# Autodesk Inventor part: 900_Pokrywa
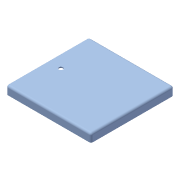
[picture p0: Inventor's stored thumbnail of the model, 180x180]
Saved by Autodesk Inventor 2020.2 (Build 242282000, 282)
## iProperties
Created: 2006-01
Part Number: 900_Pokrywa
Document SubType Name: Modeling
Designer: F.Stasiak
Density: 1 g/cm^3
Material: Ogólny
Appearance: Niebieski pastelowy
Manager: www.cadconsulting.pl
Company: Fabian Stasiak CAD Consulting
Author: F.Stasiak
Subject: Zbiór ćwiczeń. Autodesk Inventor 2020. Kurs podstawowy
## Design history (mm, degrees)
sketch "Szkic1"
  geometry: L1 (205, 200)-(-205, 200); L2 (-205, 200)-(-205, -200); L3 (-205, -200)-(205, -200); L4 (205, -200)-(205, 200); L5 (205, 0)-(-205, 0); 2 further points
  constraints: 10 end point, 3 midpoint, 2 parallel, 1 coincident, 1 horizontal, 1 perpendicular
  dimensions: "d0" = 410 distance of L2.end L3.end; "d1" = 400 distance of L1.end L2.end
extrude "Wyciągnięcie proste1" new body sketch "Szkic1" distance "d2" = 40; taper "d3" = 0 deg
fillet "Zaokrąglenie1" dims "d4" = 10
feature "Skorupa1" dims "d5" = 5
sketch "Szkic2"
  geometry: C1 r 10 at (-140, 0); 1 further point
  constraints: 1 centre point
  dimensions: "d6" = 20 diameter of C1; "d7" = 140 distance of point (0, 0) C1.centre; "d8" = 0 vertical distance of point (0, 0) C1.centre
extrude "Wyciągnięcie proste2" cut sketch "Szkic2" extent not by distance; stored distance "d9" = 10; taper "d10" = 0 deg
fillet "Zaokrąglenie2" dims "d11" = 10
fillet "Zaokrąglenie3" dims "d12" = 5
node "Bryła1"
node "Korpusy bryłowe"
node "Korpusy powierzchniowe"
